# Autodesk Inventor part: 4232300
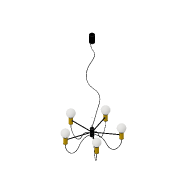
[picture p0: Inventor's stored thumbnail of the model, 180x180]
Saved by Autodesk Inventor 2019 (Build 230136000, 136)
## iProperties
Created: 2020-11
Part Number: 4232300
Material: Generic
Document SubType Name: Modeling
Designer: user
Density: 1 g/cm^3
Appearance: Default
Author: user
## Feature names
1. Revolution1
2. Revolution2
3. Revolution3
4. Revolution4
5. Revolution5
6. Extrusion1
7. Extrusion2
8. Extrusion3
9. Extrusion4
10. Extrusion5
11. Sweep1
12. Revolution6
13. Revolution7
14. Mirror2
15. Mirror3
16. Extrusion7
17. Sweep2
18. Fillet1
19. Fillet2
20. Fillet3
21. Fillet4
22. Fillet5
23. Fillet6
24. Revolution8
25. Extrusion8
26. Extrusion9
27. Extrusion10
28. Extrusion11
29. Sweep3
30. Circular Pattern1
31. Extrusion12
32. Extrusion13
33. Extrusion14
34. Extrusion15
35. Sweep5
36. Extrusion16
37. Fillet7
38. Fillet8
## Parameters: d0 = 5 mm, d1 = 299.15 mm, d3 = 2 mm, d11 = 128.35 mm, d13 = 22.5 mm, d19 = 4 mm, d20 = 2 mm, d22 = 35 mm, d25 = 1065 mm, d26 = 3 mm, d27 = 2 mm, d32 = 2 mm, d33 = 0.5 mm, d34 = 1065 mm, d44 = 2 mm, d46 = 2 mm, d47 = 90 deg, d51 = 5 mm, d52 = 299.15 mm, d53 = 2 mm, d54 = 128.35 mm, d55 = 22.5 mm, d57 = 4 mm, d58 = 2 mm, d59 = 2 mm, d60 = 35 mm, d62 = 1065 mm, d63 = 3 mm, d64 = 2 mm, d66 = 2 mm, d67 = 0.5 mm, d68 = 1065 mm, d69 = 22.5 mm, d71 = 2 mm, d72 = 35 mm, d74 = 128.3 mm, d75 = 2 mm, d76 = 2 mm, d79 = 2 mm, d80 = 90 deg, d81 = 5 mm, d82 = 299.15 mm, d83 = 2 mm, d84 = 128.35 mm, d85 = 22.5 mm, d87 = 4 mm, d88 = 2 mm, d89 = 2 mm, d90 = 35 mm, d92 = 1065 mm, d93 = 3 mm, d94 = 2 mm, d96 = 2 mm, d97 = 0.5 mm, d98 = 1065 mm, d99 = 22.5 mm, d101 = 2 mm, d102 = 35 mm, d104 = 128.3 mm, d105 = 2 mm, d106 = 2 mm, d107 = 22.5 mm, d109 = 2 mm, d110 = 2 mm, d112 = 90 deg, d142 = 5 mm, d143 = 299.15 mm, d144 = 2 mm, d145 = 128.35 mm, d146 = 22.5 mm, d148 = 4 mm, d149 = 2 mm, d150 = 2 mm, d151 = 35 mm, d153 = 1065 mm, d154 = 3 mm, d155 = 2 mm, d157 = 2 mm, d158 = 0.5 mm, d159 = 1065 mm, d160 = 22.5 mm, d162 = 2 mm, d163 = 35 mm, d165 = 128.3 mm, d166 = 2 mm, d167 = 2 mm, d168 = 22.5 mm, d170 = 2 mm, d171 = 2 mm, d172 = 90 deg, d173 = 5 mm, d174 = 299.15 mm, d175 = 2 mm, d176 = 128.35 mm, d177 = 22.5 mm, d179 = 4 mm, d180 = 2 mm, d181 = 2 mm, d182 = 35 mm, d184 = 1065 mm, d185 = 3 mm, d186 = 2 mm, d188 = 2 mm, d189 = 1 mm, d190 = 1065 mm, d191 = 22.5 mm, d193 = 2 mm, d194 = 35 mm, d196 = 128.3 mm, d197 = 2 mm, d198 = 2 mm, d199 = 22.5 mm, d201 = 2 mm, d202 = 2 mm, d203 = 90 deg, d204 = 5 mm, d205 = 2 mm, d206 = 0, d207 = 0.5 mm, d208 = 279.2 mm, d209 = 22.5 mm, d211 = 2 mm, d212 = 0, d214 = 2 mm, d215 = 0, d216 = 2 mm, d217 = 0, d218 = 5 mm, d220 = 2 mm, d221 = 0, d222 = 5 mm, d223 = 299.15 mm, d224 = 2 mm, d225 = 128.35 mm, d226 = 22.5 mm, d228 = 4 mm, d229 = 2 mm, d230 = 2 mm, d231 = 35 mm, d233 = 1065 mm, d234 = 3 mm, d235 = 2 mm, d237 = 2 mm, d238 = 0.5 mm, d239 = 1065 mm, d241 = 2 mm, d242 = 2 mm, d244 = 2 mm, d245 = 279.2 mm, d246 = 22.5 mm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
